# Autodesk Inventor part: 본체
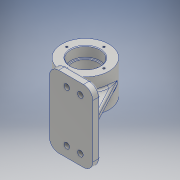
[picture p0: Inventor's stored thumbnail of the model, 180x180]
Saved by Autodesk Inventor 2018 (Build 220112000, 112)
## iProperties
Created: 2023-08
Part Number: 본체
Material: 알루미늄 6061
Document SubType Name: Modeling
Designer: home
Density: 2.7 g/cm^3
Appearance: 알루미늄 - 평지
Mass: 777.806 g
Surface Area: 536.474 cm^2
Volume: 288.076 cm^3
Author: home
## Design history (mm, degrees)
sketch "스케치1"
  geometry: L1 (35, -58)-(-35, -58); L2 (-35, -58)-(-35, 58); L3 (-35, 58)-(35, 58); L4 (35, 58)-(35, -58); 3 further points
  constraints: 8 end point, 2 midpoint, 2 parallel, 1 horizontal, 1 horizontal alignment, 1 perpendicular, 1 vertical alignment
  dimensions: "d0" = 70 distance of L1.start L1.end; "d1" = 116 distance of L1.end L2.end
extrude "돌출1" new body sketch "스케치1" distance "d2" = 12; taper "d3" = 0 deg
sketch "스케치2"
  geometry: L1 (-7, 41)-(15, 41); L2 (-7, 31)-(15, 31); L3 (15, 51)-(-7, 51); L4 (35, -58)-(35, 58) reference; A1 r 10 centre (-7, 41) between (-7, 51) and (-7, 31); A2 r 10 centre (15, 41) between (15, 31) and (15, 51); 2 further points
  constraints: 8 end point, 4 point on circle, 4 tangent, 2 centre point, 1 horizontal, 1 midpoint, 1 parallel
  dimensions: "d4" = 10 radius of A2; "d5" = 22 distance of L2.start L2.end; "d6" = 41 vertical distance of point (4, 41) point (0, 0); "d8" = 20 distance from line of L4 L1.end
extrude "돌출2" join sketch "스케치2" distance "d9" = 3; taper "d10" = 0 deg
sketch "스케치3"
  geometry: C1 r 4.5 at (-7, 41); C2 r 4.5 at (15, 41); A1 r 10 centre (15, 41) between (15, 31) and (15, 51) reference; A2 r 10 centre (-7, 41) between (-7, 51) and (-7, 31) reference; 1 further point
  constraints: 2 centre point, 2 coincident, 1 equal radius
  dimensions: "d11" = 9 diameter of C2
extrude "돌출3" cut sketch "스케치3" extent not by distance; stored distance "d12" = 0; taper "d13" = 0 deg
fillet "모깎기1" dims "d14" = 3
node "작업 평면1"
sketch "스케치4"
  geometry: L1 (6.062, 70)-(109.938, 70); L2 (31, 70)-(31, 108); L3 (31, 108)-(85, 108); L4 (85, 108)-(85, 70); L5 (31, 70)-(85, 70); 3 further points
  constraints: 10 end point, 3 midpoint, 2 perpendicular, 2 point on line, 2 vertical alignment, 1 collinear, 1 horizontal, 1 vertical
  dimensions: "d16" = 70 distance of point (58, 0) point (58, 70); "d17" = 76 diameter of L3 L1; "d18" = 54 distance of L2.end L3.end; "d83" = 24.93752 distance from line of L1.end L4
revolve "회전1" sketch "스케치4" stored, may be unused: angle "d19" = 90 deg
sketch "스케치5"
  geometry: C1 r 38 at (0, 0) reference; C2 r 20.5 at (0, 0); 1 further point
  constraints: 1 centre point, 1 coincident
  dimensions: "d20" = 41 diameter of C2
extrude "돌출4" cut sketch "스케치5" extent not by distance; stored distance "d21" = 3; taper "d22" = 0 deg
sketch "스케치6"
  geometry: C1 r 20.5 at (0, 0) reference; C2 r 38 at (0, 0) reference; C3 r 23.5 at (0, 0); 1 further point
  constraints: 1 centre point, 1 coincident
  dimensions: "d23" = 47 diameter of C3
extrude "돌출5" cut sketch "스케치6" distance "d24" = 17; taper "d25" = 0 deg
node "작업 평면2"
sketch "스케치7"
  geometry: L1 (-85, 27)-(-9, 27) reference; L2 (-85, -27)-(-9, -27) reference; C1 r 8 at (-47, 0); 2 further points
  constraints: 1 centre point, 1 horizontal alignment, 1 midpoint, 1 vertical alignment
  dimensions: "d27" = 16 diameter of C1
extrude "돌출6" join sketch "스케치7" stored distance "d28" = 17; taper "d29" = 0 deg
sketch "스케치8"
  geometry: C1 r 8 at (0, 0) reference; C2 r 3.5 at (0, 0); 1 further point
  constraints: 1 centre point, 1 coincident
  dimensions: "d30" = 7 diameter of C2
extrude "돌출7" cut sketch "스케치8" distance "d31" = 4; taper "d32" = 0 deg
sketch "스케치9"
  geometry: C1 r 3.5 at (0, 0) reference; 1 further point
hole "구멍1" sketch "스케치9" at (0, 0) diameter "d33" = 5.188; stored, may be unused: countersink angle "d37" = 90 deg, drill point angle "d39" = 118 deg; dims "d34" = 20, "d35" = 4, "d36" = 2, "d38" = 20
chamfer "모따기1" distance "d40" = 1; stored, may be unused: second distance "d41" = 2, angle "d42" = 45 deg
fillet "모깎기2" dims "d43" = 1
sketch "스케치10"
  geometry: L1 (0, 0)-(30, 0); C1 r 38 at (0, 0) reference; 1 further point
  constraints: 2 end point, 1 horizontal
  dimensions: "d44" = 30 distance of L1.start L1.end
hole "구멍2" sketch "스케치10" at (30, 0) diameter "d45" = 3.242; stored, may be unused: countersink angle "d49" = 90 deg, drill point angle "d51" = 118 deg; dims "d46" = 8, "d47" = 4, "d48" = 2, "d50" = 10
fillet "모깎기3" dims "d55" = 3
sketch "스케치11"
  geometry: L1 (31, 108)-(31, 32) reference; L2 (39.534, 39)-(76.466, 39); L3 (85, 108)-(85, 32) reference; L4 (116, 12)-(0, 12) reference; L5 (22, 12)-(39.534, 39); L6 (76.466, 39)-(94, 12); L7 (0, 0)-(0, 12) reference; L8 (116, 0)-(116, 12) reference; 1 further point
  constraints: 6 end point, 2 point on line, 1 horizontal
  dimensions: "d56" = 33 deg angle of L7 L5; "d57" = 33 deg angle of L8 L6; "d58" = 22 distance from line of L7 L5.start; "d59" = 22 distance from line of L8 L6.end; "d60" = 27 distance between parallel lines of L4 L2
feature "리브1" sketch "스케치11" dims "d61" = 1, "d62" = 8, "d63" = 0, "d64" = 0, "d65" = 1, "d66" = 1
sketch "스케치12"
  geometry: L1 (-13.471, 87.882)-(27, 12); L2 (35, 12)-(-35, 12) reference; L3 (35, 0)-(35, 12) reference; L4 (-35, 12)-(-27, 12) reference; L5 (27, 12)-(-35, 12); 2 further points
  constraints: 4 end point, 1 horizontal, 1 point on line, 3 other
  dimensions: "d67" = 8 distance from line of L3 L1.end
feature "리브2" sketch "스케치12" dims "d68" = 1, "d69" = 12, "d70" = 0, "d71" = 0, "d72" = 1, "d73" = 1
fillet "모깎기4" dims "d74" = 15
fillet "모깎기5" dims "d75" = 3
fillet "모깎기6" dims "d76" = 3
fillet "모깎기7" dims "d77" = 3
fillet "모깎기8" dims "d78" = 3
sketch "스케치13"
  geometry: L1 (26.979, 25.778)-(59.021, 25.778); L2 (59.021, 25.778)-(59.021, 12.222); L3 (59.021, 12.222)-(26.979, 12.222); L4 (26.979, 12.222)-(26.979, 25.778); L5 (86, 0)-(0, 0) reference; 4 further points
  constraints: 3 midpoint, 1 vertical, 1 vertical alignment, 2 other
  dimensions: "d79" = 19 distance from line of L5 point (26.979, 19); "d84" = 25.77819 distance between parallel lines of L1 L5; "d85" = 32.04238 distance between parallel lines of L2 L4
feature "엠보싱1" sketch "스케치13" dims "d0" = 70, "d1" = 116, "d80" = 0.5, "d81" = 0
fillet "모깎기9" dims "d82" = 3
node "솔리드1"
mirror "미러1"
mirror "미러2"
pattern_circular "원형 패턴1" dims angle "d53" = 360 deg
mirror "미러3"
node "투영된 루프1"
node "투영된 루프2"
node "투영된 루프3"
node "투영된 루프4"
other parameters: "d15" = -82, "d26" = -111
